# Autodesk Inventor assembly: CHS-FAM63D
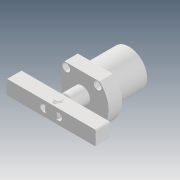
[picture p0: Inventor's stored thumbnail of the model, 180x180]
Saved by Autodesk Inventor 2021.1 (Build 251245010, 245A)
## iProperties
Created: 2019-05
Part Number: CHS-FAM63D
Description: STEP AP203
Document SubType Name: Assembly
Designer: user
Title: CHS-FAM63D.STEP
Revision Number: ÈÎºÎ
Sending System: SolidWorks 2017
Preprocessor: SwSTEP 2.0
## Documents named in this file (6)
- D:\Vault_2016\Projekty\Clamptek\Hydraulic\CHS\CHS-63\Inventor\CHS-FAM63D\CHS-FAM63D.iam
- D:\Vault_2016\Projekty\Clamptek\Hydraulic\CHS\CHS-63\Inventor\CHS-FAM63D\CHS-FAM63BT.ipt
- D:\Vault_2016\Projekty\Clamptek\Hydraulic\CHS\CHS-63\Inventor\CHS-FAM63D\¶ÌÏú.ipt
- D:\Vault_2016\Projekty\Clamptek\Hydraulic\CHS\CHS-63\Inventor\CHS-FAM63D\¿¨»É.ipt
- D:\Vault_2016\Projekty\Clamptek\Hydraulic\CHS\CHS-63\Inventor\CHS-FAM63D\CHS-63D-01.ipt
- D:\Vault_2016\Projekty\Clamptek\Hydraulic\CHS\CHS-63\Inventor\CHS-FAM63D\CHS-63D»îÈû¸Ë_1.ipt
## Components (6 placed, 6 different names)
1. CHS-FAM63BT_1
2. ¶ÌÏú_2
3. ¿¨»É_3
4. CHS-63D-01_4
5. ¿¨»É_5
6. CHS-63D»îÈû¸Ë_1_6
